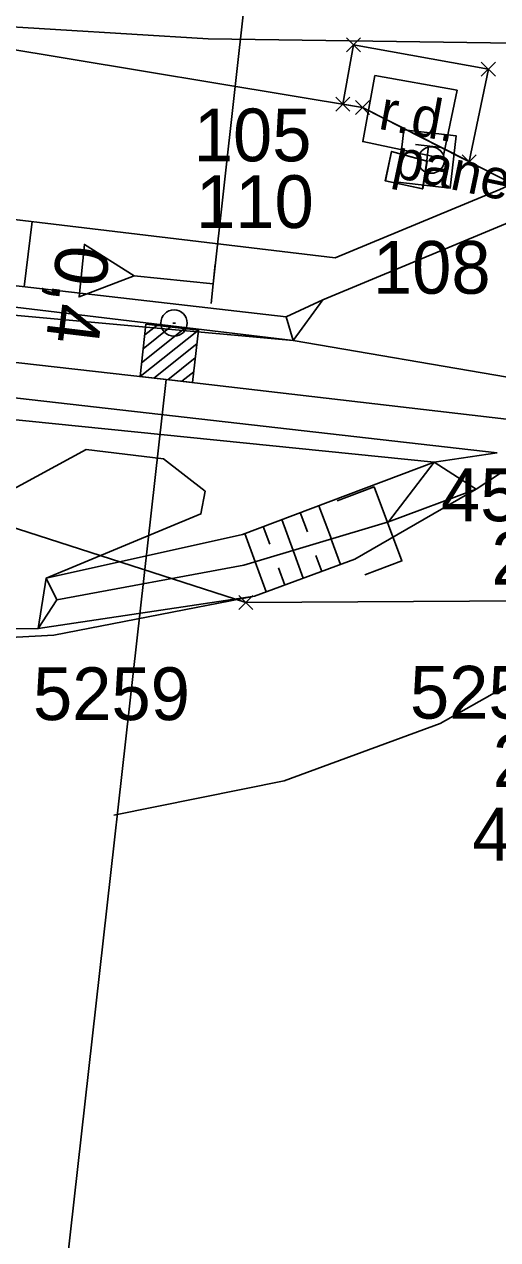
# Model space of a CAD drawing. Extents: x -804899 to -803847, y -1165742 to -1164942.
# Drawn here: x -804789.9 to -804771.96, y -1165146.47 to -1165100.4 of the extents above; entities that cross this region are included whole.
import ezdxf

# ---------------------------------------------------------------- set-up
doc = ezdxf.new("R2010")
doc.units = 0
for name, color, linetype in [('0381KM061-064P - Vrstva 1', 7, 'Continuous'), ('0381KM061-064P - Vrstva 16', 7, 'Continuous'), ('0381KM061-064P - Vrstva 23', 7, 'Continuous'), ('0381KM061-064P - Vrstva 27', 7, 'Continuous'), ('0381KM061-064P - Vrstva 3', 7, 'Continuous'), ('0381KM061-064P - Vrstva 33', 7, 'Continuous'), ('0381KM061-064P - Vrstva 4', 7, 'Continuous'), ('0381KM061-064P - Vrstva 43', 7, 'Continuous'), ('0381KM061-064P - Vrstva 48', 7, 'Continuous'), ('0381KM061-064P - Vrstva 49', 7, 'Continuous'), ('0381KM061-064P - Vrstva 51', 7, 'Continuous'), ('0381KM061-064P - Vrstva 8', 7, 'Continuous'), ('DZ - DZ_číslo', 7, 'Continuous'), ('szdc - hran DP', 7, 'Continuous'), ('szdc - szdc_cislo', 7, 'Continuous'), ('szdc - szdc_krizek', 7, 'Continuous'), ('TZ - TZ_cislo', 7, 'Continuous'), ('TZ - TZ_krizek', 7, 'Continuous'), ('TZ - TZ_zpf', 7, 'Continuous'), ('VB - VB_cislo', 7, 'Continuous')]:
    doc.layers.add(name, color=color, linetype=linetype)

msp = doc.modelspace()

# ---------------------------------------------------------------- linework, layer by layer
at = {"layer": '0381KM061-064P - Vrstva 1'}
for points in [[(-804844.65, -1165107.068), (-804836.778, -1165107.957), (-804807.434, -1165111.276), (-804784.52, -1165113.87), (-804783.453, -1165113.99)], [(-804783.453, -1165113.99), (-804769.784, -1165115.585), (-804758.243, -1165117.11), (-804750.67, -1165118.27), (-804748.021, -1165118.722)]]:
    msp.add_lwpolyline(points, dxfattribs=at)
at = {"layer": '0381KM061-064P - Vrstva 16'}
for p, q in [((-804775.98, -1165105.22), (-804775.98, -1165105.22)), ((-804774.64, -1165105.59), (-804774.63, -1165105.59)), ((-804776.21, -1165106.34), (-804776.22, -1165106.34))]:
    msp.add_line(p, q, dxfattribs=at)
for points in [[(-804774.8, -1165106.64), (-804776.22, -1165106.34), (-804775.98, -1165105.22), (-804774.63, -1165105.59), (-804774.8, -1165106.64)], [(-804774.81, -1165106.64), (-804774.64, -1165105.59), (-804775.98, -1165105.22), (-804776.21, -1165106.34), (-804774.81, -1165106.64), (-804774.8, -1165106.64)], [(-804799.348, -1165123.41), (-804799.304, -1165121.51), (-804793.654, -1165119.83), (-804787.557, -1165116.523), (-804784.627, -1165116.879), (-804783.047, -1165118.104), (-804783.205, -1165118.965), (-804789.075, -1165121.401), (-804789.371, -1165123.309), (-804799.348, -1165123.41)]]:
    msp.add_lwpolyline(points, dxfattribs=at)
at = {"layer": '0381KM061-064P - Vrstva 23'}
msp.add_lwpolyline([(-804776.62, -1165102.34), (-804773.501, -1165102.906), (-804774.038, -1165105.496), (-804777.074, -1165104.848), (-804776.62, -1165102.34)], dxfattribs=at)
at = {"layer": '0381KM061-064P - Vrstva 27'}
for p, q in [((-804774.53, -1165105.544), (-804774.43, -1165105.556)), ((-804784.276, -1165111.726), (-804784.176, -1165111.726))]:
    msp.add_line(p, q, dxfattribs=at)
for centre in [(-804774.48, -1165105.55), (-804784.226, -1165111.726)]:
    msp.add_circle(centre, 0.5, dxfattribs=at)
at = {"layer": '0381KM061-064P - Vrstva 3'}
for p, q in [((-804784.884, -1165111.816), (-804785.336, -1165112.177)), ((-804783.303, -1165111.994), (-804785.514, -1165113.758)), ((-804783.829, -1165111.935), (-804785.455, -1165113.232)), ((-804784.357, -1165111.876), (-804785.395, -1165112.704)), ((-804783.362, -1165112.521), (-804784.987, -1165113.817)), ((-804783.421, -1165113.049), (-804784.459, -1165113.877)), ((-804783.481, -1165113.575), (-804783.933, -1165113.936)), ((-804784.52, -1165113.87), (-804789.793, -1165160.754))]:
    msp.add_line(p, q, dxfattribs=at)
msp.add_lwpolyline([(-804783.526, -1165113.982), (-804785.514, -1165113.758), (-804785.29, -1165111.771), (-804783.303, -1165111.994)], close=True, dxfattribs=at)
at = {"layer": '0381KM061-064P - Vrstva 33'}
for p, q in [((-804775.079, -1165104.955), (-804774.085, -1165105.071)), ((-804774.582, -1165105.013), (-804774.698, -1165106.007))]:
    msp.add_line(p, q, dxfattribs=at)
msp.add_lwpolyline([(-804775.517, -1165104.401), (-804773.531, -1165104.633), (-804773.763, -1165106.619), (-804775.749, -1165106.387), (-804775.517, -1165104.401)], dxfattribs=at)
at = {"layer": '0381KM061-064P - Vrstva 4'}
for points in [[(-804843.453, -1165105.104), (-804840.343, -1165105.456), (-804819.518, -1165107.917), (-804802.69, -1165109.638), (-804779.709, -1165112.392)], [(-804843.833, -1165105.728), (-804840.797, -1165106.06), (-804819.65, -1165108.38), (-804802.702, -1165110.303), (-804779.709, -1165112.392), (-804771.588, -1165113.785)], [(-804845.413, -1165108.319), (-804841.864, -1165108.694), (-804820.526, -1165111.132), (-804802.924, -1165113.128), (-804771.984, -1165116.641)], [(-804845.698, -1165108.787), (-804841.902, -1165109.222), (-804820.576, -1165111.743), (-804803.207, -1165114.08), (-804774.362, -1165117.007), (-804771.984, -1165116.641)]]:
    msp.add_lwpolyline(points, dxfattribs=at)
at = {"layer": '0381KM061-064P - Vrstva 43'}
msp.add_lwpolyline([(-804778.049, -1165118.463), (-804776.644, -1165117.937), (-804775.592, -1165120.747), (-804776.997, -1165121.273)], dxfattribs=at)
at = {"layer": '0381KM061-064P - Vrstva 48'}
for p, q in [((-804789.607, -1165107.883), (-804789.9, -1165110.351)), ((-804778.264, -1165119.915), (-804778.739, -1165118.651)), ((-804779.705, -1165120.344), (-804780.143, -1165119.178)), ((-804779.167, -1165119.644), (-804779.441, -1165118.914)), ((-804781.146, -1165120.773), (-804781.547, -1165119.705)), ((-804780.593, -1165120.112), (-804780.845, -1165119.442)), ((-804778.275, -1165119.918), (-804777.919, -1165120.88)), ((-804779.715, -1165120.347), (-804779.326, -1165121.4)), ((-804778.846, -1165120.536), (-804778.623, -1165121.14)), ((-804781.156, -1165120.777), (-804780.733, -1165121.92)), ((-804780.273, -1165121.001), (-804780.03, -1165121.66))]:
    msp.add_line(p, q, dxfattribs=at)
at = {"layer": '0381KM061-064P - Vrstva 49'}
for points in [[(-804782.933, -1165100.952), (-804770.452, -1165101.128), (-804760.766, -1165096.165), (-804750.377, -1165086.376), (-804747.774, -1165080.287)], [(-804778.125, -1165109.25), (-804771.874, -1165106.665), (-804764.298, -1165103.24), (-804757.01, -1165099.37), (-804754.139, -1165096.348)], [(-804814.349, -1165098.182), (-804791.62, -1165100.427), (-804782.933, -1165100.952)], [(-804840.644, -1165103.216), (-804836.045, -1165101.514), (-804816.03, -1165105.177), (-804802.019, -1165106.406), (-804778.125, -1165109.25)], [(-804843.18, -1165104.657), (-804835.928, -1165105.502), (-804818.934, -1165107.357), (-804802.317, -1165108.928), (-804779.974, -1165111.488)], [(-804843.453, -1165105.104), (-804840.343, -1165105.456), (-804819.518, -1165107.917), (-804802.69, -1165109.638), (-804779.709, -1165112.392)], [(-804778.59, -1165110.844), (-804770.535, -1165107.501)], [(-804779.709, -1165112.392), (-804779.974, -1165111.488), (-804778.59, -1165110.844)], [(-804778.59, -1165110.844), (-804779.709, -1165112.392)], [(-804789.075, -1165121.401), (-804781.631, -1165119.737), (-804774.362, -1165117.007)], [(-804776.096, -1165119.269), (-804774.362, -1165117.007)], [(-804774.362, -1165117.007), (-804772.772, -1165118.025)], [(-804781.178, -1165122.085), (-804777.377, -1165120.679), (-804772.772, -1165118.025)], [(-804776.096, -1165119.269), (-804772.772, -1165118.025)], [(-804788.671, -1165122.219), (-804781.584, -1165120.904), (-804776.096, -1165119.269)], [(-804789.371, -1165123.309), (-804789.075, -1165121.401)], [(-804789.075, -1165121.401), (-804788.671, -1165122.219), (-804789.371, -1165123.309)], [(-804789.371, -1165123.309), (-804781.178, -1165122.085)]]:
    msp.add_lwpolyline(points, dxfattribs=at)
at = {"layer": '0381KM061-064P - Vrstva 51'}
for points in [[(-804799.401, -1165124.127), (-804788.787, -1165123.564), (-804781.178, -1165122.085), (-804777.377, -1165120.679), (-804772.772, -1165118.025), (-804766.254, -1165113.723), (-804759.193, -1165108.078), (-804752.39, -1165104.15), (-804745.737, -1165101.091), (-804737.367, -1165099.155), (-804728.561, -1165098.534)], [(-804786.505, -1165130.38), (-804780.047, -1165129.084), (-804774.134, -1165126.908), (-804767.616, -1165123.226), (-804757.446, -1165115.319), (-804754.899, -1165113.701), (-804749.494, -1165110.738), (-804743.99, -1165108.455), (-804736.292, -1165106.603), (-804728.9, -1165105.899)]]:
    msp.add_lwpolyline(points, dxfattribs=at)
at = {"layer": '0381KM061-064P - Vrstva 8'}
for p, q in [((-804782.747, -1165110.241), (-804774.889, -1165040.201)), ((-804787.621, -1165108.745), (-804785.732, -1165109.94)), ((-804782.823, -1165110.987), (-804782.671, -1165109.495))]:
    msp.add_line(p, q, dxfattribs=at)
msp.add_lwpolyline([(-804782.747, -1165110.241), (-804785.732, -1165109.94), (-804787.822, -1165110.735), (-804787.621, -1165108.745), (-804785.732, -1165109.94)], dxfattribs=at)
at = {"layer": 'szdc - hran DP'}
for p, q in [((-804818.68, -1165096.66), (-804777.08, -1165103.56)), ((-804777.08, -1165103.56), (-804771.09, -1165106.6)), ((-804781.51, -1165122.32), (-804791.88, -1165118.97)), ((-804765.27, -1165122.22), (-804781.51, -1165122.32))]:
    msp.add_line(p, q, dxfattribs=at)
at = {"layer": 'szdc - szdc_krizek'}
for p, q in [((-804776.815, -1165103.825), (-804777.346, -1165103.295)), ((-804777.346, -1165103.825), (-804776.815, -1165103.295)), ((-804781.245, -1165122.585), (-804781.776, -1165122.055)), ((-804781.776, -1165122.585), (-804781.245, -1165122.055))]:
    msp.add_line(p, q, dxfattribs=at)
at = {"layer": 'TZ - TZ_krizek'}
for p, q in [((-804777.161, -1165101.443), (-804777.692, -1165100.913)), ((-804777.692, -1165101.443), (-804777.161, -1165100.913)), ((-804772.049, -1165102.371), (-804772.58, -1165101.841)), ((-804772.58, -1165102.371), (-804772.049, -1165101.841)), ((-804777.569, -1165103.7), (-804778.1, -1165103.17)), ((-804778.1, -1165103.7), (-804777.569, -1165103.17)), ((-804776.815, -1165103.825), (-804777.346, -1165103.295)), ((-804777.346, -1165103.825), (-804776.815, -1165103.295)), ((-804772.775, -1165105.875), (-804773.306, -1165105.345)), ((-804773.306, -1165105.875), (-804772.775, -1165105.345))]:
    msp.add_line(p, q, dxfattribs=at)
at = {"layer": 'TZ - TZ_zpf'}
for points in [[(-804777.834, -1165103.435), (-804777.426, -1165101.178)], [(-804777.426, -1165101.178), (-804772.314, -1165102.106), (-804773.04, -1165105.61)]]:
    msp.add_lwpolyline(points, dxfattribs=at)
msp.add_lwpolyline([(-804777.834, -1165103.435), (-804777.426, -1165101.178), (-804772.314, -1165102.106), (-804773.04, -1165105.61), (-804777.08, -1165103.56)], close=True, dxfattribs=at)

# ---------------------------------------------------------------- texts
at = {"layer": '0381KM061-064P - Vrstva 16'}
msp.add_text('panel.', height=1.5, rotation=348.0707, dxfattribs=at).set_placement((-804775.996, -1165106.177))
at = {"layer": '0381KM061-064P - Vrstva 23'}
msp.add_text('r.d.', height=1.5, rotation=349.7146, dxfattribs=at).set_placement((-804776.522, -1165104.359))
at = {"layer": '0381KM061-064P - Vrstva 48'}
msp.add_text('0,4', height=2, rotation=263.1664, dxfattribs=at).set_placement((-804788.642, -1165108.699))
at = {"layer": 'DZ - DZ_číslo'}
for s, p in [('218', (-804772.198, -1165121.641)), ('220', (-804772.146, -1165129.316))]:
    msp.add_text(s, height=2, dxfattribs=at).set_placement(p)
at = {"layer": 'szdc - szdc_cislo'}
for s, p in [('5259', (-804789.573, -1165126.779)), ('5258', (-804775.286, -1165126.722))]:
    msp.add_text(s, height=2, dxfattribs=at).set_placement(p)
at = {"layer": 'TZ - TZ_cislo'}
for s, p in [('105', (-804783.479, -1165105.597)), ('110', (-804783.392, -1165108.125)), ('108', (-804776.69, -1165110.617))]:
    msp.add_text(s, height=2, dxfattribs=at).set_placement(p)
at = {"layer": 'VB - VB_cislo'}
for s, p in [('457', (-804774.109, -1165119.241)), ('456', (-804772.921, -1165132.103))]:
    msp.add_text(s, height=2, dxfattribs=at).set_placement(p)

doc.saveas('drawing.dxf')
